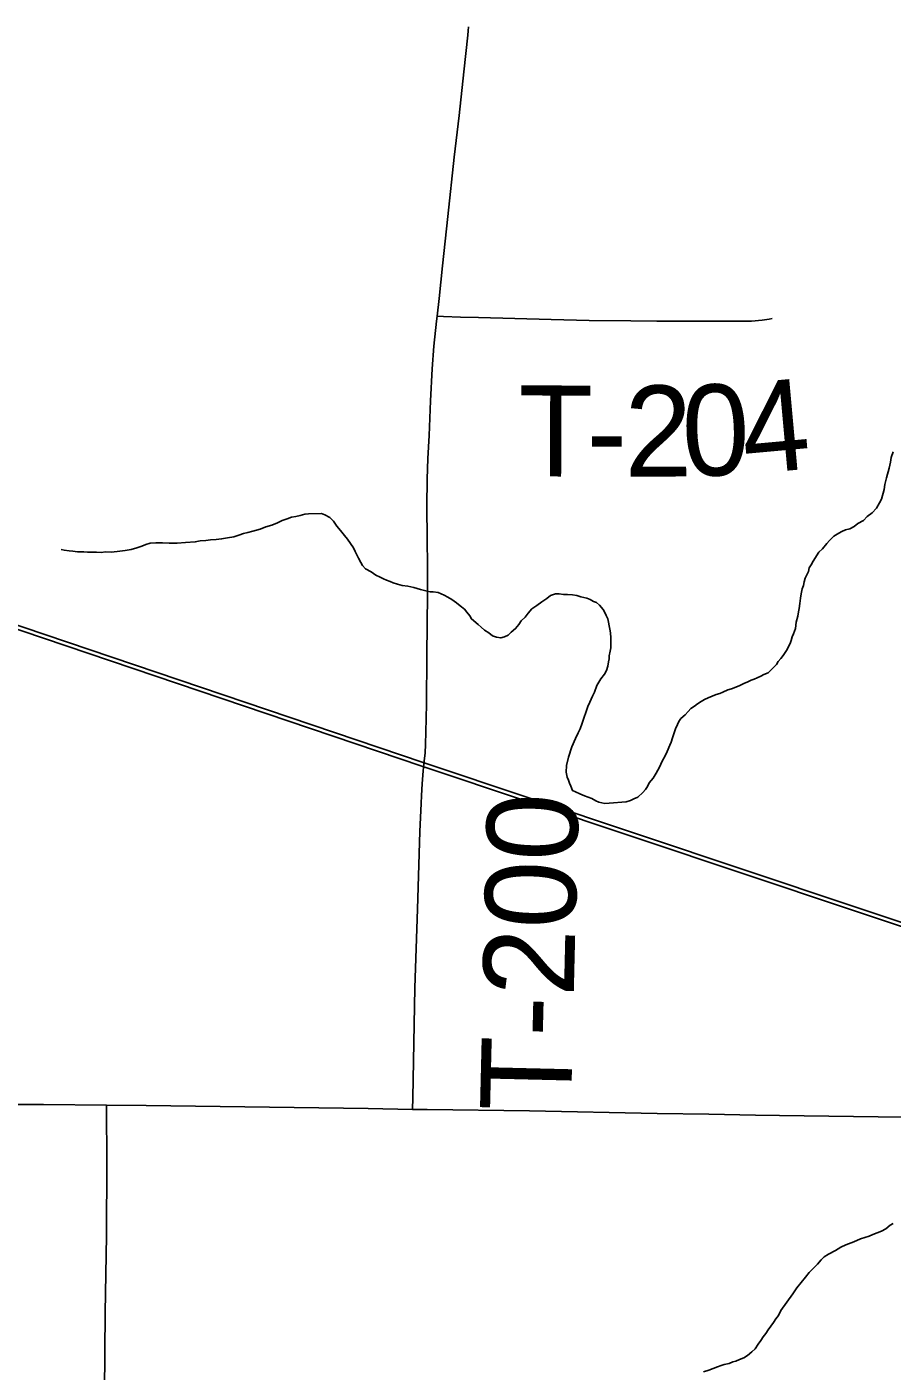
# Model space of a CAD drawing. Extents: x 2.1 to 73.9, y 4 to 26.
# Drawn here: x 46.1036 to 46.3737, y 22.5087 to 22.9283 of the extents above; entities that cross this region are included whole.
import ezdxf

# ---------------------------------------------------------------- set-up
doc = ezdxf.new("R2010")
doc.units = 0
for name, color, linetype in [('GM_X_County_Road', 7, 'Continuous'), ('GM_X_Minor_River', 7, 'Continuous'), ('GM_X_Rail_Line', 7, 'Continuous'), ('GM_X_Township_Road', 7, 'Continuous'), ('GM_X_Township_Road_Text', 7, 'Continuous')]:
    doc.layers.add(name, color=color, linetype=linetype)

msp = doc.modelspace()

# ---------------------------------------------------------------- linework, layer by layer
at = {"layer": 'GM_X_County_Road'}
for points in [[(45.71502, 22.59241), (45.72836, 22.59222), (45.74638, 22.59184), (45.77248, 22.59184), (45.78523, 22.59185), (45.80948, 22.59178), (45.84087, 22.59181), (45.86015, 22.5919), (45.8788, 22.59179), (45.89931, 22.59179), (45.91423, 22.59186), (45.92325, 22.5919), (45.94221, 22.59173), (45.96366, 22.59182), (45.99972, 22.59193), (46.02241, 22.59179), (46.05629, 22.59178), (46.08925, 22.5919), (46.10883, 22.5919), (46.12842, 22.59173)], [(46.12633, 22.3373), (46.12632, 22.33924), (46.12634, 22.35105), (46.12629, 22.35757), (46.12639, 22.37001), (46.12653, 22.38151), (46.12664, 22.39426), (46.12683, 22.40856), (46.12694, 22.42596), (46.12703, 22.43373), (46.12706, 22.44244), (46.12735, 22.45798), (46.12758, 22.47227), (46.12758, 22.47693), (46.12757, 22.48314), (46.12771, 22.49309), (46.1278, 22.50211), (46.12806, 22.52698), (46.12844, 22.55091), (46.12848, 22.55899), (46.12854, 22.56583), (46.12855, 22.57547), (46.12844, 22.58919), (46.12842, 22.59173)], [(46.12842, 22.59173), (46.14085, 22.59162), (46.21017, 22.59065), (46.22396, 22.5904)], [(46.22396, 22.5904), (46.22851, 22.59031), (46.26052, 22.5899), (46.30031, 22.58916), (46.31647, 22.5889), (46.33107, 22.58857), (46.33853, 22.58853), (46.36931, 22.58808), (46.38298, 22.58792), (46.40909, 22.58764), (46.42681, 22.58742), (46.4467, 22.58716), (46.46131, 22.58683), (46.4756, 22.58666), (46.4843, 22.58657), (46.49985, 22.58648), (46.53839, 22.58602), (46.56202, 22.58592), (46.57383, 22.58579), (46.59994, 22.58519), (46.61796, 22.58499), (46.62194, 22.58495), (46.63588, 22.58476)]]:
    msp.add_lwpolyline(points, dxfattribs=at)
at = {"layer": 'GM_X_Minor_River'}
for points in [[(46.37397, 22.79561), (46.37336, 22.79392), (46.37313, 22.7924), (46.3727, 22.79051), (46.37187, 22.7875), (46.37144, 22.78542), (46.37121, 22.78391), (46.37037, 22.78089), (46.36977, 22.77977), (46.36878, 22.77808), (46.36742, 22.7766), (46.36587, 22.7755), (46.3647, 22.7742), (46.36296, 22.77329), (46.3618, 22.77237), (46.36045, 22.77165), (46.35912, 22.7713), (46.35796, 22.77076), (46.357, 22.77021), (46.35546, 22.7693), (46.3541, 22.76801), (46.35331, 22.76708), (46.35194, 22.7654), (46.35077, 22.76429), (46.34899, 22.76149), (46.3484, 22.76037), (46.3478, 22.75943), (46.34759, 22.7583), (46.34658, 22.75623), (46.34618, 22.75511), (46.34596, 22.75397), (46.34555, 22.75284), (46.34532, 22.75133), (46.3451, 22.75001)], [(46.28539, 22.73196), (46.28562, 22.73347), (46.28583, 22.73442), (46.28587, 22.73593), (46.28591, 22.73764), (46.28576, 22.73917), (46.2856, 22.74031), (46.28492, 22.74355), (46.28437, 22.74452), (46.28402, 22.74548), (46.28347, 22.74644), (46.28237, 22.7478), (46.28144, 22.74858), (46.2805, 22.74898), (46.27937, 22.74958), (46.27843, 22.74999), (46.27654, 22.75041), (46.27523, 22.75083), (46.2739, 22.75105), (46.27238, 22.75109), (46.27105, 22.75112), (46.26973, 22.75135), (46.26859, 22.75137), (46.26706, 22.75084), (46.26589, 22.74992), (46.26435, 22.74882), (46.2628, 22.74772), (46.26125, 22.74662), (46.26008, 22.74532), (46.2591, 22.74402), (46.25793, 22.74291), (46.25715, 22.74179), (46.25616, 22.74049), (46.25481, 22.73938), (46.25383, 22.73846), (46.25268, 22.73792), (46.25153, 22.73756), (46.25021, 22.73779), (46.24889, 22.7382), (46.24777, 22.73918), (46.24646, 22.73997), (46.24535, 22.74095), (46.24442, 22.74173), (46.24237, 22.74349), (46.24183, 22.74446), (46.24091, 22.74562), (46.24017, 22.74659), (46.23887, 22.74757), (46.23775, 22.74855), (46.23626, 22.74954), (46.23495, 22.75033), (46.23382, 22.75093), (46.23288, 22.75133), (46.23194, 22.75173), (46.23043, 22.75196), (46.22948, 22.75199), (46.22854, 22.7522), (46.22646, 22.75263), (46.22438, 22.75326), (46.22249, 22.75368), (46.22079, 22.75392), (46.21928, 22.75433), (46.21796, 22.75475), (46.21702, 22.75515), (46.21589, 22.75556), (46.21495, 22.75596), (46.21383, 22.75656), (46.21251, 22.75716), (46.21102, 22.75815), (46.20934, 22.75914), (46.20841, 22.76012), (46.20786, 22.76108), (46.20714, 22.76243), (46.20605, 22.76454), (46.20551, 22.7657), (46.2046, 22.76705), (46.20368, 22.7684), (46.20276, 22.76957), (46.20147, 22.77112), (46.20036, 22.77247), (46.19926, 22.77402), (46.19815, 22.77519), (46.19665, 22.77599), (46.19552, 22.7764), (46.19153, 22.77631), (46.19039, 22.77615), (46.18886, 22.7758), (46.18752, 22.77546), (46.18619, 22.7753), (46.18485, 22.77477), (46.18331, 22.77424), (46.18178, 22.77352), (46.18005, 22.7728), (46.17814, 22.77228), (46.17641, 22.77156), (46.17411, 22.77086), (46.17258, 22.77052), (46.17124, 22.77017), (46.16971, 22.76964), (46.16818, 22.76911), (46.16627, 22.76878)], [(46.16627, 22.76878), (46.16437, 22.76845), (46.16265, 22.7683), (46.16094, 22.76816), (46.15941, 22.768), (46.1577, 22.76786), (46.15617, 22.76752), (46.15313, 22.7674), (46.15047, 22.76709), (46.148, 22.76715), (46.14591, 22.76721), (46.14382, 22.76726), (46.14211, 22.76711), (46.14077, 22.76677), (46.13943, 22.76623), (46.1379, 22.7657), (46.13617, 22.76518), (46.13426, 22.76484), (46.13179, 22.76453), (46.12989, 22.76438), (46.12818, 22.76443), (46.12684, 22.76427), (46.12533, 22.76431), (46.12381, 22.76435), (46.12248, 22.76438), (46.12134, 22.76441), (46.12039, 22.76443), (46.11944, 22.76446), (46.11793, 22.76469), (46.11679, 22.76472), (46.11527, 22.76494), (46.11433, 22.76516)], [(46.3451, 22.75001), (46.34487, 22.7483), (46.34464, 22.74679), (46.34442, 22.74566), (46.3442, 22.74433), (46.34377, 22.74244), (46.34353, 22.74055), (46.34292, 22.73886), (46.34252, 22.73792), (46.34211, 22.73679), (46.3419, 22.73584), (46.3413, 22.73491), (46.3409, 22.73397), (46.34031, 22.73304), (46.33971, 22.7321), (46.33893, 22.73117), (46.33815, 22.73024), (46.33755, 22.72931), (46.33502, 22.72671), (46.33368, 22.72618), (46.33271, 22.72563), (46.33156, 22.72509), (46.3306, 22.72474), (46.32964, 22.72438), (46.32868, 22.72384), (46.32734, 22.7233), (46.32618, 22.72276), (46.32484, 22.72222), (46.3235, 22.72169), (46.32235, 22.72134), (46.32081, 22.72062), (46.31985, 22.72026), (46.31871, 22.71991), (46.31755, 22.71937), (46.31621, 22.71883), (46.31506, 22.71829), (46.31409, 22.71775), (46.31294, 22.71702), (46.31197, 22.71628), (46.31081, 22.71555), (46.31003, 22.71462), (46.30905, 22.71351), (46.30769, 22.7124), (46.3071, 22.71147), (46.3067, 22.71053), (46.30609, 22.70921), (46.30568, 22.7079), (46.30507, 22.70639), (46.30466, 22.70507), (46.30426, 22.70413), (46.30345, 22.70207), (46.30284, 22.70075), (46.30185, 22.69907), (46.30104, 22.69719), (46.30005, 22.69532), (46.29906, 22.69382), (46.29788, 22.69233), (46.29729, 22.69121), (46.29669, 22.69027), (46.29591, 22.68934), (46.29435, 22.68786), (46.29301, 22.68733), (46.29205, 22.68678), (46.29071, 22.68644), (46.28538, 22.686), (46.28405, 22.68585), (46.2831, 22.68606), (46.28216, 22.68627), (46.28122, 22.68668), (46.27991, 22.68747), (46.27765, 22.68829), (46.27615, 22.68889), (46.27483, 22.6895), (46.27389, 22.6899), (46.27336, 22.69124), (46.273, 22.6922), (46.27264, 22.69316), (46.27229, 22.69412), (46.27195, 22.69565), (46.272, 22.69774), (46.27263, 22.70038), (46.27366, 22.70358), (46.27487, 22.70621), (46.27567, 22.7079), (46.27627, 22.70921), (46.27689, 22.71091), (46.2775, 22.71279), (46.27811, 22.71429), (46.27873, 22.71618), (46.27933, 22.71749), (46.27973, 22.71843), (46.28014, 22.71937), (46.28074, 22.72068), (46.28155, 22.72275), (46.28274, 22.72481), (46.28392, 22.7263), (46.28452, 22.72742), (46.28493, 22.72874), (46.28515, 22.73007), (46.28537, 22.73101), (46.28539, 22.73196)], [(46.37403, 22.55481), (46.37307, 22.55426), (46.37171, 22.55316), (46.37036, 22.55243), (46.36902, 22.5519), (46.36767, 22.55136), (46.36652, 22.55082), (46.36384, 22.54994), (46.36173, 22.54904), (46.35924, 22.54816), (46.3577, 22.54744), (46.35596, 22.54634), (46.35385, 22.54525), (46.35249, 22.54434), (46.35152, 22.54341), (46.35035, 22.54211), (46.34918, 22.54081), (46.34782, 22.53952), (46.34664, 22.53803), (46.34527, 22.53636), (46.3439, 22.53468), (46.34271, 22.53281), (46.33897, 22.52759), (46.33817, 22.52609), (46.33739, 22.52497), (46.3366, 22.52385), (46.33581, 22.52273), (46.33502, 22.52161), (46.33423, 22.52049), (46.33345, 22.51937), (46.33266, 22.51825), (46.33187, 22.51714), (46.33089, 22.51564), (46.32991, 22.51472), (46.32855, 22.51361), (46.3274, 22.51288), (46.32605, 22.51234), (46.3249, 22.5118), (46.32395, 22.51164), (46.32279, 22.5111), (46.32127, 22.51076), (46.32031, 22.5104), (46.31916, 22.51005), (46.31782, 22.50952), (46.31647, 22.50898), (46.31475, 22.50845)]]:
    msp.add_lwpolyline(points, dxfattribs=at)
at = {"layer": 'GM_X_Rail_Line'}
for points in [[(45.54219, 22.90652), (45.58425, 22.9028), (45.62519, 22.89476), (45.66973, 22.88493), (45.71592, 22.8692), (45.83842, 22.8289), (46.2269, 22.69751), (46.56199, 22.58544), (46.63635, 22.56054), (46.67107, 22.55071), (46.70186, 22.54481), (46.72642, 22.54022), (46.75459, 22.53662), (46.78407, 22.53465), (47.14078, 22.52875), (47.4739, 22.52318), (47.52958, 22.52286), (47.57085, 22.52154), (47.60951, 22.52417), (47.66355, 22.52712), (47.72775, 22.53236), (47.77492, 22.53662), (48.02673, 22.55714)], [(45.54225, 22.90776), (45.58442, 22.90404), (45.62544, 22.89598), (45.67007, 22.88613), (45.71631, 22.87038), (45.83882, 22.83008), (46.2273, 22.69868), (46.56238, 22.58662), (46.63671, 22.56173), (46.67135, 22.55192), (46.70209, 22.54603), (46.72662, 22.54145), (46.75471, 22.53786), (46.78412, 22.5359), (47.1408, 22.53), (47.47391, 22.52443), (47.52961, 22.5241), (47.57083, 22.52279), (47.60943, 22.52541), (47.66347, 22.52836), (47.72765, 22.5336), (47.77482, 22.53786), (48.0292, 22.55847)]]:
    msp.add_lwpolyline(points, dxfattribs=at)
at = {"layer": 'GM_X_Township_Road'}
for points in [[(46.23162, 22.83798), (46.23226, 22.84347), (46.23332, 22.85367), (46.23497, 22.86913), (46.23702, 22.88767), (46.2385, 22.90065), (46.24004, 22.91424), (46.24124, 22.92568), (46.24137, 22.92708), (46.24148, 22.9283)], [(46.22396, 22.5904), (46.22404, 22.59404), (46.2247, 22.62836), (46.22552, 22.65291), (46.22624, 22.67715), (46.22663, 22.68585), (46.22676, 22.68833), (46.22698, 22.69205), (46.2273, 22.69607), (46.22765, 22.69916), (46.22788, 22.70162), (46.22803, 22.70441), (46.22816, 22.70813), (46.22835, 22.71684), (46.22847, 22.73207), (46.22861, 22.75134), (46.22862, 22.76005), (46.22855, 22.76844), (46.22849, 22.7787), (46.22855, 22.78708), (46.22876, 22.79361), (46.22913, 22.80075), (46.22959, 22.81162), (46.23014, 22.82155), (46.23066, 22.82868), (46.23144, 22.8364), (46.23162, 22.83798)], [(46.23162, 22.83798), (46.23364, 22.83791), (46.23897, 22.83771), (46.24456, 22.83753), (46.26725, 22.83691), (46.27906, 22.83665), (46.29212, 22.83649), (46.3002, 22.83643), (46.31015, 22.83641), (46.32507, 22.83642), (46.32973, 22.83648), (46.33314, 22.83671), (46.33529, 22.83704), (46.3362, 22.83725)]]:
    msp.add_lwpolyline(points, dxfattribs=at)

# ---------------------------------------------------------------- texts
at = {"layer": 'GM_X_Township_Road_Text'}
for s, height, rotation, p in [('4', 0.02841, 5.1863, (46.32784, 22.78858)), ('T', 0.02841, 359.7686, (46.25701, 22.788)), ('2', 0.02841, 0.2524, (46.29018, 22.78788)), ('0', 0.02841, 1.6221, (46.30842, 22.78797)), ('-', 0.02841, 359.8392, (46.27829, 22.78791)), ('T-200', 0.028409, 88.6241, (46.27342, 22.58957))]:
    msp.add_text(s, height=height, rotation=rotation, dxfattribs=at).set_placement(p)

doc.saveas('drawing.dxf')
